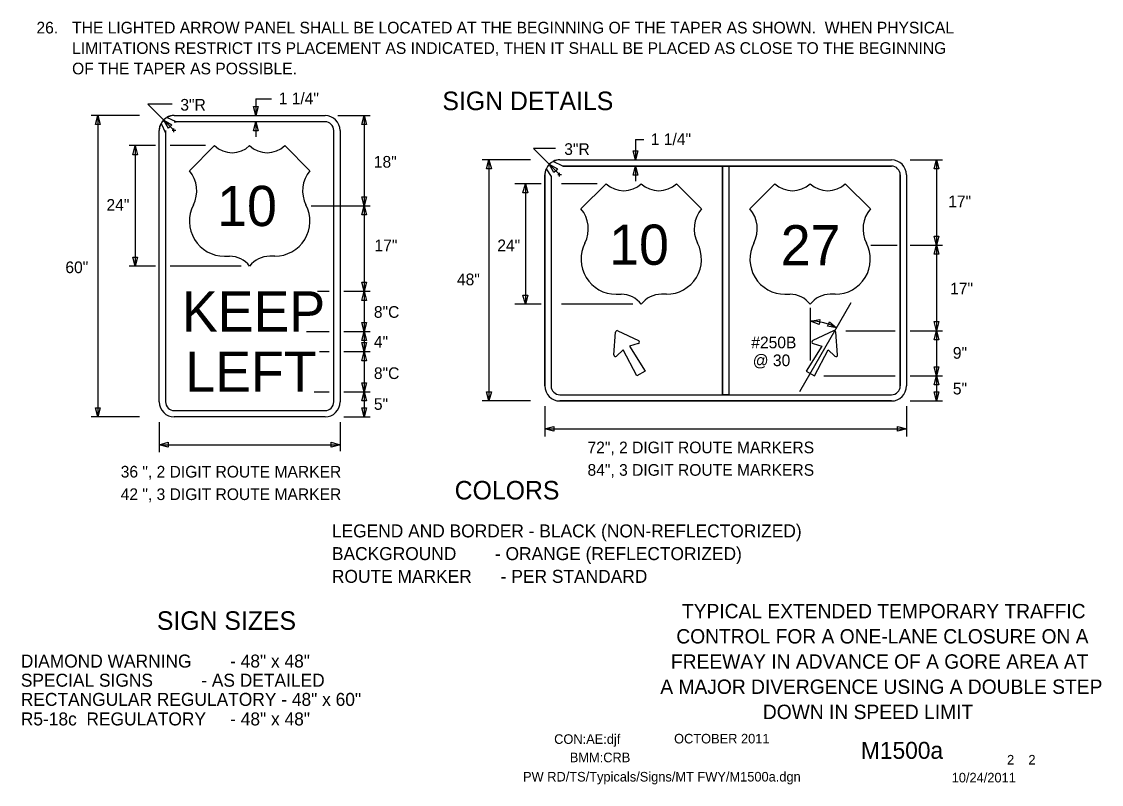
# Model space of a CAD drawing. Extents: x 16284 to 18474, y 5417 to 6974.
# Drawn here: x 17775 to 18474, y 5932 to 6425 of the extents above; entities that cross this region are included whole.
import ezdxf

# ---------------------------------------------------------------- set-up
doc = ezdxf.new("R2010")
doc.units = 0
for name, color, linetype in [('BORDER', 7, 'Continuous'), ('BORDER_SIGNAL_WO', 7, 'Continuous'), ('TRAFFIC_SIGNS_PR', 7, 'Continuous'), ('TYPICAL_EX', 7, 'Continuous'), ('TYPICAL_TEXT_DIMEN_PR', 7, 'Continuous')]:
    doc.layers.add(name, color=color, linetype=linetype)

msp = doc.modelspace()

# ---------------------------------------------------------------- linework, layer by layer
at = {"layer": 'TRAFFIC_SIGNS_PR'}
for p, q in [((17866.33, 6360.97), (17865.33, 6359.46)), ((17865.36, 6359.39), (17868.23, 6353.35)), ((17875.12, 6360.53), (17869.02, 6363.27)), ((17873.92, 6364.59), (17971.42, 6364.59)), ((17971.42, 6360.53), (17873.92, 6360.53)), ((17864.17, 6179.34), (17864.17, 6354.84)), ((17868.23, 6354.84), (17868.23, 6179.34)), ((17977.1, 6179.34), (17977.1, 6354.84)), ((17981.17, 6354.84), (17981.17, 6179.34)), ((18125.39, 6331.84), (18119.16, 6334.86)), ((18123.44, 6335.89), (18337.94, 6335.89)), ((18123.44, 6335.89), (18337.94, 6335.89)), ((18125.38, 6331.83), (18228.66, 6331.83)), ((18337.94, 6331.83), (18125.38, 6331.83)), ((18228.66, 6331.83), (18228.66, 6183.95)), ((18232.72, 6331.83), (18232.72, 6183.95)), ((18232.72, 6331.83), (18337.94, 6331.83)), ((18113.69, 6326.14), (18113.69, 6189.64)), ((18113.69, 6189.64), (18113.69, 6326.14)), ((18114.61, 6330.15), (18117.74, 6325.11)), ((18117.75, 6325.09), (18117.75, 6189.64)), ((18117.75, 6325.09), (18117.75, 6189.64)), ((18343.62, 6326.14), (18343.62, 6280.39)), ((18343.63, 6189.64), (18343.63, 6326.14)), ((18347.69, 6326.14), (18347.69, 6189.64)), ((18347.69, 6326.14), (18347.69, 6189.64)), ((18343.62, 6280.39), (18343.62, 6189.64)), ((18158.29, 6209.75), (18159.44, 6224.47)), ((18160.95, 6225.34), (18174.27, 6218.98)), ((18300.42, 6225.34), (18287.11, 6218.98)), ((18303.08, 6209.75), (18301.94, 6224.47)), ((18123.44, 6183.95), (18337.94, 6183.95)), ((18123.44, 6179.89), (18337.94, 6179.89)), ((18337.94, 6179.89), (18123.44, 6179.89)), ((17873.92, 6173.65), (17971.42, 6173.65)), ((17971.42, 6169.59), (17873.92, 6169.59))]:
    msp.add_line(p, q, dxfattribs=at)
for points in [[(18125.38, 6331.83), (18125.36, 6331.84)], [(18117.74, 6325.11), (18117.75, 6325.09)], [(18174.1, 6217.01), (18168.38, 6215.43), (18178.6, 6199.26), (18173.2, 6196.14), (18164.31, 6213.08), (18160.08, 6208.91)], [(18287.27, 6217.01), (18292.99, 6215.43), (18282.78, 6199.26), (18288.17, 6196.14), (18297.07, 6213.08), (18301.29, 6208.91)]]:
    msp.add_lwpolyline(points, dxfattribs=at)
msp.add_lwpolyline([(18228.66, 6331.83), (18232.72, 6331.83), (18232.72, 6183.95), (18228.66, 6183.95)], close=True, dxfattribs=at)
for centre, radius, start, end in [((17871.2, 6355.43), 7.06, 145.86811, 184.82317), ((17873.92, 6354.84), 9.75, 90, 180), ((17873.33, 6357.01), 7.6, 85.58319, 124.53531), ((17874.52, 6364.95), 4.47, 262.2432, 277.7568), ((17971.42, 6354.84), 9.75, 0, 90), ((17971.42, 6354.84), 5.69, 0, 90), ((17862.77, 6354.1), 5.51, 352.24294, 7.75653), ((18123.44, 6326.14), 9.75, 90, 180), ((18123.44, 6326.14), 9.75, 90, 180), ((18122.76, 6329.33), 6.6, 84.11162, 123.06374), ((18124.38, 6339.01), 7.24, 277.81035, 278.05403), ((18337.94, 6326.14), 9.75, 0, 90), ((18337.94, 6326.14), 9.75, 0, 90), ((18337.94, 6326.14), 5.69, 0, 89.99421), ((18337.94, 6326.14), 5.69, 0, 90), ((18119.82, 6326.85), 6.17, 147.60925, 186.56283), ((18160.5, 6224.38), 1.06, 64.48226, 175.51774), ((18173.81, 6218.02), 1.06, 285.9885, 64.48226), ((18287.56, 6218.02), 1.06, 115.51774, 254.0115), ((18300.88, 6224.38), 1.06, 4.48226, 115.51774), ((18159.35, 6209.67), 1.06, 175.51775, 314.01151), ((18302.03, 6209.67), 1.06, 225.98849, 4.48225), ((18123.44, 6189.64), 9.75, 180, 270), ((18123.44, 6189.64), 9.75, 180, 270), ((18123.44, 6189.64), 5.69, 180, 270), ((18123.44, 6189.64), 5.69, 180, 270), ((18337.94, 6189.64), 9.75, 270, 0), ((18337.94, 6189.64), 5.69, 270, 0), ((18337.94, 6189.64), 9.75, 270, 0), ((18337.94, 6189.64), 5.69, 270, 0), ((17873.92, 6179.34), 9.75, 180, 270), ((17873.92, 6179.34), 5.69, 180, 270), ((17971.42, 6179.34), 5.69, 270, 0), ((17971.42, 6179.34), 9.75, 270, 0)]:
    msp.add_arc(centre, radius, start, end, dxfattribs=at)
at = {"layer": 'TYPICAL_EX'}
for p, q in [((17883.67, 6328.84), (17899.92, 6345.09)), ((17961.67, 6328.84), (17945.42, 6345.09)), ((18137.05, 6304.23), (18153.3, 6320.48)), ((18215.05, 6304.23), (18198.8, 6320.48)), ((18246.33, 6304.23), (18262.58, 6320.48)), ((18324.33, 6304.23), (18308.08, 6320.48)), ((17906.39, 6273.55), (17909.64, 6273.55)), ((17938.94, 6273.55), (17935.69, 6273.55)), ((18159.78, 6248.94), (18163.03, 6248.94)), ((18192.32, 6248.94), (18189.07, 6248.94)), ((18269.05, 6248.94), (18272.3, 6248.94)), ((18301.6, 6248.94), (18298.35, 6248.94))]:
    msp.add_line(p, q, dxfattribs=at)
for centre, radius, start, end in [((17911.29, 6356.93), 16.42, 226.14041, 313.85958), ((17934.04, 6356.93), 16.42, 226.14042, 313.85959), ((17868.26, 6315.83), 20.16, 333.09768, 40.19361), ((17977.07, 6315.83), 20.16, 139.80639, 206.90233), ((18164.68, 6332.32), 16.42, 226.14041, 313.85958), ((18187.42, 6332.32), 16.42, 226.14042, 313.85959), ((18273.95, 6332.32), 16.42, 226.14041, 313.85958), ((18296.7, 6332.32), 16.42, 226.14042, 313.85959), ((17906.43, 6296.27), 22.73, 152.6698, 269.90132), ((17938.9, 6296.27), 22.73, 270.09868, 27.3302), ((18121.65, 6291.22), 20.16, 333.09768, 40.19361), ((18230.45, 6291.22), 20.16, 139.80639, 206.90233), ((18230.93, 6291.22), 20.16, 333.09768, 40.19361), ((18339.73, 6291.22), 20.16, 139.80639, 206.90233), ((18159.82, 6271.66), 22.73, 152.6698, 269.90132), ((18192.28, 6271.66), 22.73, 270.09868, 27.3302), ((18269.09, 6271.66), 22.73, 152.6698, 269.90132), ((18301.56, 6271.66), 22.73, 270.09868, 27.3302), ((17909.68, 6257.27), 16.28, 37.1038, 90.13853), ((17935.65, 6257.27), 16.28, 89.86147, 142.8962), ((18163.07, 6232.66), 16.28, 37.1038, 90.13853), ((18189.03, 6232.66), 16.28, 89.86147, 142.8962), ((18272.35, 6232.66), 16.28, 37.1038, 90.13853), ((18298.31, 6232.66), 16.28, 89.86147, 142.8962)]:
    msp.add_arc(centre, radius, start, end, dxfattribs=at)
at = {"layer": 'TYPICAL_TEXT_DIMEN_PR'}
for p, q in [((17926.64, 6375.35), (17926.64, 6364.59)), ((17926.64, 6375.35), (17936.74, 6375.35)), ((17872.54, 6371.87), (17856.88, 6371.87)), ((17856.88, 6371.87), (17867.12, 6361.64)), ((17926.64, 6364.59), (17925.07, 6370.45)), ((17925.07, 6370.45), (17926.64, 6370.45)), ((17926.64, 6370.45), (17928.21, 6370.45)), ((17928.21, 6370.45), (17926.64, 6364.59)), ((17851.34, 6364.59), (17820.04, 6364.59)), ((17822.81, 6358.73), (17824.38, 6364.59)), ((17824.38, 6358.73), (17822.81, 6358.73)), ((17824.38, 6364.59), (17824.38, 6169.59)), ((17824.38, 6364.59), (17825.95, 6358.73)), ((17825.95, 6358.73), (17824.38, 6358.73)), ((17867.12, 6361.64), (17873.67, 6355.08)), ((17870.15, 6356.38), (17867.12, 6361.64)), ((17867.12, 6361.64), (17872.37, 6358.6)), ((17872.37, 6358.6), (17871.26, 6357.49)), ((17925.12, 6354.67), (17926.69, 6360.53)), ((17926.69, 6360.53), (17926.69, 6350.78)), ((17926.69, 6360.53), (17928.26, 6354.67)), ((17979.71, 6364.59), (18000.67, 6364.59)), ((17995.2, 6358.73), (17996.77, 6364.59)), ((17996.77, 6358.73), (17995.2, 6358.73)), ((17996.77, 6364.59), (17996.77, 6306.09)), ((17996.77, 6364.59), (17998.34, 6358.73)), ((17998.34, 6358.73), (17996.77, 6358.73)), ((17871.26, 6357.49), (17870.15, 6356.38)), ((17872.47, 6355.08), (17874.88, 6355.08)), ((17873.67, 6353.87), (17873.67, 6356.29)), ((17926.69, 6354.67), (17925.12, 6354.67)), ((17928.26, 6354.67), (17926.69, 6354.67)), ((17861.79, 6345.09), (17844.67, 6345.09)), ((17846.99, 6339.23), (17848.56, 6345.09)), ((17848.56, 6345.09), (17848.56, 6267.09)), ((17848.56, 6345.09), (17850.13, 6339.23)), ((17894.03, 6345.09), (17871.16, 6345.09)), ((18172.3, 6349.04), (18172.3, 6335.89)), ((18172.3, 6349.04), (18177.82, 6349.04)), ((17848.56, 6339.23), (17846.99, 6339.23)), ((17850.13, 6339.23), (17848.56, 6339.23)), ((18120.58, 6343.18), (18106.4, 6343.18)), ((18106.4, 6343.18), (18116.55, 6333.03)), ((18172.3, 6335.89), (18170.72, 6341.75)), ((18170.72, 6341.75), (18172.3, 6341.75)), ((18172.3, 6341.75), (18173.87, 6341.75)), ((18173.87, 6341.75), (18172.3, 6335.89)), ((18104.46, 6335.89), (18073.16, 6335.89)), ((18075.93, 6330.03), (18077.5, 6335.89)), ((18077.5, 6335.89), (18077.5, 6179.89)), ((18077.5, 6335.89), (18079.07, 6330.03)), ((18116.55, 6333.03), (18123.2, 6326.38)), ((18119.58, 6327.77), (18116.55, 6333.03)), ((18116.55, 6333.03), (18121.81, 6329.99)), ((18170.77, 6325.97), (18172.34, 6331.83)), ((18170.77, 6325.97), (18172.34, 6331.83)), ((18172.34, 6331.83), (18172.34, 6322.08)), ((18172.34, 6331.83), (18173.92, 6325.97)), ((18172.34, 6331.83), (18173.92, 6325.97)), ((18350.06, 6335.89), (18371.02, 6335.89)), ((18365.55, 6330.03), (18367.12, 6335.89)), ((18367.12, 6335.89), (18367.12, 6280.64)), ((18367.12, 6335.89), (18368.69, 6330.03)), ((18077.5, 6330.03), (18075.93, 6330.03)), ((18079.07, 6330.03), (18077.5, 6330.03)), ((18120.7, 6328.88), (18119.58, 6327.77)), ((18121.81, 6329.99), (18120.7, 6328.88)), ((18121.99, 6326.38), (18124.41, 6326.38)), ((18123.2, 6325.17), (18123.2, 6327.59)), ((18172.34, 6325.97), (18170.77, 6325.97)), ((18172.34, 6325.97), (18170.77, 6325.97)), ((18173.92, 6325.97), (18172.34, 6325.97)), ((18173.92, 6325.97), (18172.34, 6325.97)), ((18367.12, 6330.03), (18365.55, 6330.03)), ((18368.69, 6330.03), (18367.12, 6330.03)), ((18111.31, 6320.48), (18094.19, 6320.48)), ((18099.48, 6314.62), (18101.06, 6320.48)), ((18101.06, 6320.48), (18101.06, 6242.48)), ((18101.06, 6320.48), (18102.63, 6314.62)), ((18147.42, 6320.48), (18124.54, 6320.48)), ((17996.77, 6306.09), (17995.2, 6311.95)), ((17995.2, 6311.95), (17996.77, 6311.95)), ((17996.77, 6311.95), (17998.34, 6311.95)), ((17998.34, 6311.95), (17996.77, 6306.09)), ((18101.06, 6314.62), (18099.48, 6314.62)), ((18102.63, 6314.62), (18101.06, 6314.62)), ((17962.56, 6306.09), (18000.67, 6306.09)), ((17995.2, 6300.23), (17996.77, 6306.09)), ((17996.77, 6306.09), (17996.77, 6250.84)), ((17996.77, 6306.09), (17998.34, 6300.23)), ((17996.77, 6300.23), (17995.2, 6300.23)), ((17998.34, 6300.23), (17996.77, 6300.23)), ((18367.12, 6280.64), (18365.55, 6286.5)), ((18365.55, 6286.5), (18367.12, 6286.5)), ((18367.12, 6286.5), (18368.69, 6286.5)), ((18368.69, 6286.5), (18367.12, 6280.64)), ((18324.5, 6280.64), (18341.65, 6280.64)), ((18350.06, 6280.64), (18371.02, 6280.64)), ((18365.55, 6274.78), (18367.12, 6280.64)), ((18367.12, 6274.78), (18365.55, 6274.78)), ((18367.12, 6280.64), (18367.12, 6225.39)), ((18367.12, 6280.64), (18368.69, 6274.78)), ((18368.69, 6274.78), (18367.12, 6274.78)), ((17848.56, 6267.09), (17846.99, 6272.95)), ((17846.99, 6272.95), (17848.56, 6272.95)), ((17848.56, 6272.95), (17850.13, 6272.95)), ((17850.13, 6272.95), (17848.56, 6267.09)), ((17861.79, 6267.09), (17844.67, 6267.09)), ((17917.16, 6267.09), (17871.16, 6267.09)), ((17996.77, 6250.84), (17995.2, 6256.7)), ((17995.2, 6256.7), (17996.77, 6256.7)), ((17996.77, 6256.7), (17998.34, 6256.7)), ((17998.34, 6256.7), (17996.77, 6250.84)), ((17966.49, 6250.84), (17974.17, 6250.84)), ((17983.54, 6250.84), (18000.67, 6250.84)), ((17995.2, 6244.98), (17996.77, 6250.84)), ((17996.77, 6250.84), (17996.77, 6224.84)), ((17996.77, 6250.84), (17998.34, 6244.98)), ((18101.06, 6242.48), (18099.48, 6248.34)), ((18099.48, 6248.34), (18101.06, 6248.34)), ((18101.06, 6248.34), (18102.63, 6248.34)), ((18102.63, 6248.34), (18101.06, 6242.48)), ((17996.77, 6244.98), (17995.2, 6244.98)), ((17998.34, 6244.98), (17996.77, 6244.98)), ((18111.31, 6242.48), (18094.19, 6242.48)), ((18170.54, 6242.48), (18124.54, 6242.48)), ((18278.72, 6185.99), (18311.96, 6243.58)), ((18285.48, 6206.15), (18285.48, 6240.14)), ((18285.51, 6231.59), (18291.5, 6232.55)), ((18291.5, 6232.55), (18291.34, 6230.98)), ((17996.77, 6224.84), (17995.2, 6230.7)), ((17995.2, 6230.7), (17996.77, 6230.7)), ((17996.77, 6230.7), (17998.34, 6230.7)), ((17998.34, 6230.7), (17996.77, 6224.84)), ((18291.17, 6229.42), (18285.51, 6231.59)), ((18291.34, 6230.98), (18291.17, 6229.42)), ((18296.49, 6228.26), (18297.17, 6229.68)), ((18302.46, 6227.13), (18296.49, 6228.26)), ((18297.17, 6229.68), (18297.86, 6231.09)), ((18297.86, 6231.09), (18302.46, 6227.13)), ((18367.12, 6225.39), (18365.55, 6231.25)), ((18365.55, 6231.25), (18367.12, 6231.25)), ((18367.12, 6231.25), (18368.69, 6231.25)), ((18368.69, 6231.25), (18367.12, 6225.39)), ((17959.48, 6224.84), (17974.17, 6224.84)), ((17983.54, 6224.84), (18000.67, 6224.84)), ((17995.2, 6218.98), (17996.77, 6224.84)), ((17996.77, 6218.98), (17995.2, 6218.98)), ((17996.77, 6224.84), (17996.77, 6211.84)), ((17996.77, 6224.84), (17998.34, 6218.98)), ((17998.34, 6218.98), (17996.77, 6218.98)), ((18308.43, 6225.39), (18340.3, 6225.39)), ((18350.06, 6225.39), (18371.02, 6225.39)), ((18365.55, 6219.53), (18367.12, 6225.39)), ((18367.12, 6219.53), (18365.55, 6219.53)), ((18367.12, 6225.39), (18367.12, 6196.14)), ((18367.12, 6225.39), (18368.69, 6219.53)), ((18368.69, 6219.53), (18367.12, 6219.53)), ((17967.83, 6211.84), (17974.17, 6211.84)), ((17983.54, 6211.84), (18000.67, 6211.84)), ((17996.77, 6211.84), (17995.2, 6217.7)), ((17995.2, 6217.7), (17996.77, 6217.7)), ((17995.2, 6205.98), (17996.77, 6211.84)), ((17996.77, 6217.7), (17998.34, 6217.7)), ((17998.34, 6217.7), (17996.77, 6211.84)), ((17996.77, 6211.84), (17996.77, 6185.84)), ((17996.77, 6211.84), (17998.34, 6205.98)), ((17996.77, 6205.98), (17995.2, 6205.98)), ((17998.34, 6205.98), (17996.77, 6205.98)), ((18367.12, 6196.14), (18365.55, 6202)), ((18365.55, 6202), (18367.12, 6202)), ((18367.12, 6202), (18368.69, 6202)), ((18368.69, 6202), (18367.12, 6196.14)), ((17996.77, 6185.84), (17995.2, 6191.7)), ((17995.2, 6191.7), (17996.77, 6191.7)), ((17996.77, 6191.7), (17998.34, 6191.7)), ((17998.34, 6191.7), (17996.77, 6185.84)), ((18294.29, 6196.14), (18340.3, 6196.14)), ((18350.06, 6196.14), (18371.02, 6196.14)), ((18365.55, 6190.28), (18367.12, 6196.14)), ((18367.12, 6196.14), (18367.12, 6179.89)), ((18367.12, 6196.14), (18368.69, 6190.28)), ((17964.33, 6185.84), (17974.17, 6185.84)), ((17983.54, 6185.84), (18000.67, 6185.84)), ((17995.2, 6179.98), (17996.77, 6185.84)), ((17996.77, 6185.84), (17996.77, 6169.59)), ((17996.77, 6185.84), (17998.34, 6179.98)), ((18077.5, 6179.89), (18075.93, 6185.75)), ((18075.93, 6185.75), (18077.5, 6185.75)), ((18077.5, 6185.75), (18079.07, 6185.75)), ((18079.07, 6185.75), (18077.5, 6179.89)), ((18367.12, 6190.28), (18365.55, 6190.28)), ((18367.12, 6179.89), (18365.55, 6185.75)), ((18365.55, 6185.75), (18367.12, 6185.75)), ((18368.69, 6190.28), (18367.12, 6190.28)), ((18367.12, 6185.75), (18368.69, 6185.75)), ((18368.69, 6185.75), (18367.12, 6179.89)), ((17996.77, 6179.98), (17995.2, 6179.98)), ((17998.34, 6179.98), (17996.77, 6179.98)), ((18104.46, 6179.89), (18073.16, 6179.89)), ((18350.06, 6179.89), (18367.19, 6179.89)), ((18350.06, 6179.89), (18371.02, 6179.89)), ((18350.06, 6179.89), (18367.19, 6179.89)), ((17824.38, 6169.59), (17822.81, 6175.45)), ((17822.81, 6175.45), (17824.38, 6175.45)), ((17824.38, 6175.45), (17825.95, 6175.45)), ((17825.95, 6175.45), (17824.38, 6169.59)), ((17996.77, 6169.59), (17995.2, 6175.45)), ((17995.2, 6175.45), (17996.77, 6175.45)), ((17996.77, 6175.45), (17998.34, 6175.45)), ((17998.34, 6175.45), (17996.77, 6169.59)), ((18113.69, 6176.55), (18113.69, 6156.99)), ((18347.69, 6176.55), (18347.69, 6156.99)), ((17851.34, 6169.59), (17820.04, 6169.59)), ((17864.17, 6166.25), (17864.17, 6146.89)), ((17981.17, 6166.25), (17981.17, 6147.35)), ((17983.54, 6169.59), (18000.67, 6169.59)), ((18113.69, 6161.92), (18119.55, 6163.49)), ((18119.55, 6163.49), (18119.55, 6161.92)), ((18341.83, 6161.92), (18341.83, 6163.49)), ((18341.83, 6163.49), (18347.69, 6161.92)), ((18113.69, 6161.92), (18347.69, 6161.92)), ((18119.55, 6160.35), (18113.69, 6161.92)), ((18119.55, 6161.92), (18119.55, 6160.35)), ((18347.69, 6161.92), (18341.83, 6160.35)), ((18341.83, 6160.35), (18341.83, 6161.92)), ((17864.17, 6151.62), (17870.03, 6153.19)), ((17864.17, 6151.62), (17981.17, 6151.62)), ((17870.03, 6150.05), (17864.17, 6151.62)), ((17870.03, 6153.19), (17870.03, 6151.62)), ((17870.03, 6151.62), (17870.03, 6150.05)), ((17975.3, 6151.62), (17975.3, 6153.19)), ((17975.3, 6153.19), (17981.17, 6151.62)), ((17981.17, 6151.62), (17975.3, 6150.05)), ((17975.3, 6150.05), (17975.3, 6151.62))]:
    msp.add_line(p, q, dxfattribs=at)
msp.add_arc((18285.67, 6197.15), 34.39, 60.74521, 90.32117, dxfattribs=at)

# ---------------------------------------------------------------- texts
at = {"layer": 'BORDER'}
for s, p in [('TYPICAL EXTENDED TEMPORARY TRAFFIC', (18202.37, 6039.3)), ('CONTROL FOR A ONE-LANE CLOSURE ON A', (18198.74, 6023)), ('FREEWAY IN ADVANCE OF A GORE AREA AT', (18195.24, 6006.7)), ('A MAJOR DIVERGENCE USING A DOUBLE STEP', (18188.37, 5990.4)), ('DOWN IN SPEED LIMIT', (18254.74, 5974.11))]:
    msp.add_text(s, height=9.3, dxfattribs=at).set_placement(p)
at = {"layer": 'BORDER_SIGNAL_WO'}
for s, height, p in [('CON:AE:djf  ', 6.2, (18119.69, 5958.06)), ('    OCTOBER 2011    ', 6.2, (18188.08, 5958.34)), ('    M1500a   ', 11, (18301.86, 5948.38)), ('BMM:CRB   ', 6.2, (18129.81, 5946.17)), (' 2    2 ', 6.2, (18410.45, 5944.7)), ('PW RD/TS/Typicals/Signs/MT FWY/M1500a.dgn      ', 6.2, (18099.55, 5933.71)), ('10/24/2011    ', 6.2, (18376.93, 5933.13))]:
    msp.add_text(s, height=height, dxfattribs=at).set_placement(p)
at = {"layer": 'TRAFFIC_SIGNS_PR'}
for s, p in [('10', (17901.64, 6293.09)), ('10', (18155.29, 6268.02)), ('27', (18266.29, 6267.66)), ('KEEP', (17878.77, 6224.84)), ('LEFT', (17881, 6185.84))]:
    msp.add_text(s, height=26, dxfattribs=at).set_placement(p)
at = {"layer": 'TYPICAL_TEXT_DIMEN_PR'}
for s, height, p in [('26.', 7.56, (17784.71, 6417.67)), ('THE LIGHTED ARROW PANEL SHALL BE LOCATED AT THE BEGINNING OF THE TAPER AS SHOWN.  WHEN PHYSICAL', 7.56, (17807.76, 6417.67)), ('LIMITATIONS RESTRICT ITS PLACEMENT AS INDICATED, THEN IT SHALL BE PLACED AS CLOSE TO THE BEGINNING', 7.56, (17807.76, 6404.44)), ('OF THE TAPER AS POSSIBLE.', 7.56, (17807.76, 6391.21)), ('1 1/4"', 7.55, (17941.44, 6371.85)), ('SIGN DETAILS', 12, (18047.39, 6368.06)), ('3"R', 7.55, (17877.8, 6367.75)), ('1 1/4"', 7.55, (18182.22, 6345.47)), ('3"R', 7.55, (18126.22, 6339.1)), ('18"', 7.55, (18003.01, 6330.86)), ('24"', 7.55, (17830.01, 6302.97)), ('17"', 7.55, (18374.7, 6305.25)), ('17"', 7.55, (18003.46, 6276.81)), ('24"', 7.55, (18082.91, 6276.81)), ('60"', 7.55, (17803.41, 6262.61)), ('48"', 7.55, (18056.8, 6254.79)), ('17"', 7.55, (18375.9, 6248.89)), ('8"C', 7.55, (18003.04, 6233.7)), ('4" ', 7.55, (18003.04, 6214.44)), ('#250B', 7.55, (18247.25, 6213.98)), ('9"', 7.55, (18377.68, 6207.24)), ('@ 30', 7.55, (18248.19, 6202.43)), ('8"C', 7.55, (18003.04, 6194.11)), ('5"', 7.55, (18377.68, 6184.14)), ('5" ', 7.55, (18003.04, 6174.14)), ('72", 2 DIGIT ROUTE MARKERS', 7.55, (18141.27, 6146.06)), ('36 ", 2 DIGIT ROUTE MARKER', 7.55, (17839.21, 6130.36)), ('84", 3 DIGIT ROUTE MARKERS', 7.55, (18141.27, 6131.51)), ('COLORS', 12, (18055.33, 6116.17)), ('42 ", 3 DIGIT ROUTE MARKER', 7.55, (17839.21, 6115.81)), ('LEGEND AND BORDER - BLACK (NON-REFLECTORIZED)', 8.4, (17975.9, 6091.65)), ('BACKGROUND        - ORANGE (REFLECTORIZED)', 8.4, (17975.9, 6076.94)), ('ROUTE MARKER      - PER STANDARD', 8.4, (17975.9, 6062.24)), ('SIGN SIZES', 12, (17862.62, 6031.84)), ('DIAMOND WARNING        - 48" x 48"', 8.4, (17774.58, 6007.44)), ('SPECIAL SIGNS          - AS DETAILED', 8.4, (17774.58, 5995.04)), ('RECTANGULAR REGULATORY - 48" x 60"', 8.4, (17774.58, 5982.64)), ('R5-18c  REGULATORY     - 48" x 48"', 8.4, (17774.58, 5969.99))]:
    msp.add_text(s, height=height, dxfattribs=at).set_placement(p)

doc.saveas('drawing.dxf')
